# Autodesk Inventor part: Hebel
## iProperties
Shininess: 64.0
Length Units: 11269
Angle Units: 11279
Time Units: 11290
Mass Units: 11283
Length Display Precision: 3
Angle Display Precision: 2
Compacted: True
Part Number: Hebel
Document SubType Name: Modeling
Created: 2005-08
Material: Standard
Designer: Kumpf
Density: 0.0
Volumn: 0.0
Area: 0.0
PropertySet Name: Model Information
Control State: 0
Master: False
Checked Out: False
Author: Kumpf
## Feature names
1. Extrusion1
2. Bohrung1 [Hole]
3. Bohrung2 [Hole]
4. Extrusion2
5. Fase1 [Chamfer]
6. Rundung8 [Fillet]
7. Rundung10 [Fillet]
8. Fase2 [Chamfer]
